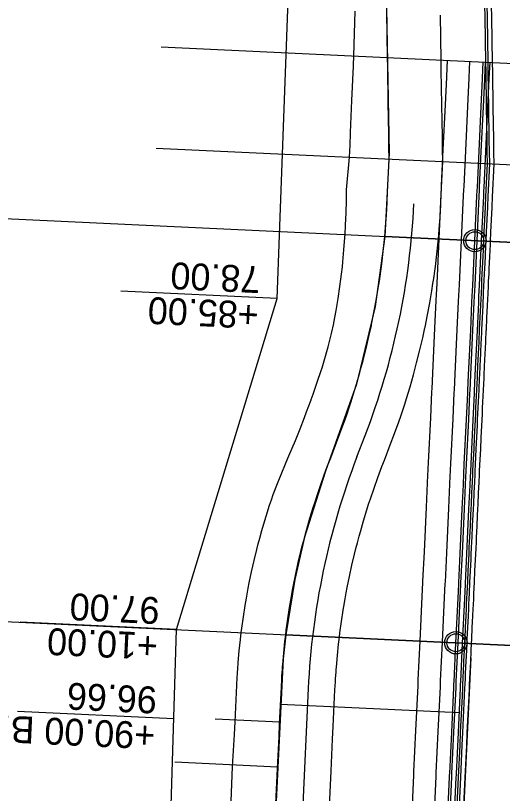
# Model space of a CAD drawing. Extents: x -70 to 701944, y -4 to 666871.
# Drawn here: x 668150.5 to 668259.3, y 654822.3 to 654996.3 of the extents above; entities that cross this region are included whole.
import ezdxf

# ---------------------------------------------------------------- set-up
doc = ezdxf.new("R2010")
doc.units = 0
for name, color, linetype in [('R_Detour', 7, 'Continuous'), ('R_Draft', 7, 'Continuous'), ('R_Drive', 7, 'Continuous'), ('R_No Plot', 7, 'Continuous'), ('R_Proposed Const Limits', 7, 'Continuous'), ('R_Proposed Road', 7, 'Continuous'), ('R_ROW', 7, 'Continuous'), ('R_ROW Annot', 7, 'Continuous'), ('R_Temp Easement Annot', 7, 'Continuous'), ('R_Water', 7, 'Continuous'), ('T_Indications', 7, 'Continuous')]:
    doc.layers.add(name, color=color, linetype=linetype)

msp = doc.modelspace()

# ---------------------------------------------------------------- linework, layer by layer
at = {"layer": 'R_Detour'}
for p, q in [((668141.87, 654951.19), (668287.62, 654944.31)), ((668134.69, 654861.43), (668283.38, 654854.41))]:
    msp.add_line(p, q, dxfattribs=at)
at = {"layer": 'R_Draft'}
msp.add_line((668181.94, 654966.65), (668374.52, 654957.56), dxfattribs=at)
at = {"layer": 'R_Drive'}
for p, q in [((668249.68, 654840.35), (668209.73, 654842.23)), ((668209.07, 654828.25), (668186.07, 654829.34))]:
    msp.add_line(p, q, dxfattribs=at)
at = {"layer": 'R_No Plot'}
for p, q in [((668183.01, 654989.3), (668375.59, 654980.21)), ((668226.79, 654897.57), (668228.65, 654902.41)), ((668215.9, 654845.79), (668212.3, 654769.57)), ((668209.54, 654838.24), (668195.13, 654838.92))]:
    msp.add_line(p, q, dxfattribs=at)
for points in [[(668285.78, 655094.57), (668215.37, 655097.89), (668216.15, 655093.84), (668225.15, 655058.76), (668230.84, 655034.55), (668233.09, 655014.27), (668233.65, 654985.81), (668233.98, 654965.53), (668233.02, 654946.89), (668287.62, 654944.31), (668288.46, 654962.05), (668284.23, 655062.51)], [(668287.62, 654944.31), (668233.02, 654946.89), (668230.85, 654931.25), (668226.69, 654913.85), (668219.8, 654894.39), (668215.11, 654879.67), (668212.9, 654870.19), (668210.9, 654857.84), (668283.38, 654854.41)], [(668210.9, 654857.84), (668210.34, 654852.46), (668208.34, 654812.91), (668206.56, 654775.07), (668206.14, 654761), (668206.78, 654747.91), (668278.19, 654744.54), (668283.38, 654854.41)]]:
    msp.add_lwpolyline(points, close=True, dxfattribs=at)
for centre in [(668253.16, 654945.94), (668248.92, 654856.04)]:
    msp.add_circle(centre, 2.5, dxfattribs=at)
for centre, start, end in [((668073.72, 654962.02), 338.9555, 357.2978), ((668381.72, 654837.96), 158.9555, 177.2978)]:
    msp.add_arc(centre, 166, start, end, dxfattribs=at)
at = {"layer": 'R_Proposed Const Limits'}
msp.add_lwpolyline([(668198.67, 654820.55), (668199, 654828.36), (668199.44, 654835.49), (668199.44, 654835.52), (668199.57, 654838.35), (668199.95, 654846.54), (668200.04, 654848.34), (668200.09, 654849.1), (668200.19, 654850.53), (668200.2, 654850.67), (668200.23, 654851.07), (668200.23, 654851.11), (668200.27, 654851.65), (668200.49, 654854.2), (668200.76, 654856.75), (668200.94, 654858.31), (668201.07, 654859.29), (668201.42, 654861.83), (668201.82, 654864.36), (668202.1, 654866), (668202.1, 654866.04), (668202.26, 654866.89), (668202.51, 654868.24), (668202.74, 654869.4), (668203.26, 654871.91), (668203.82, 654874.41), (668204.42, 654876.91), (668204.74, 654878.15), (668205.07, 654879.39), (668205.48, 654880.87), (668205.48, 654880.88), (668205.76, 654881.86), (668206.49, 654884.32), (668207.26, 654886.77), (668207.68, 654888.02), (668208.1, 654889.2), (668209.02, 654891.63), (668209.98, 654894.03), (668210.65, 654895.64), (668210.65, 654895.65), (668210.98, 654896.43), (668211.59, 654897.85), (668213.05, 654901.26), (668214.09, 654903.83), (668215.08, 654906.42), (668215.56, 654907.67), (668216.08, 654909.02), (668216.58, 654910.37), (668216.58, 654910.39), (668217.03, 654911.64), (668217.94, 654914.27), (668218.8, 654916.91), (668219, 654917.52), (668219.62, 654919.56), (668220.36, 654922.23), (668221.04, 654924.9), (668221.11, 654925.19), (668221.11, 654925.19), (668221.63, 654927.41), (668221.67, 654927.59), (668222.19, 654930.29), (668222.63, 654933), (668223.01, 654935.72), (668223.22, 654937.34), (668223.36, 654938.45), (668223.54, 654940.09), (668223.54, 654940.09), (668223.65, 654941.18), (668223.9, 654943.91), (668224.1, 654946.66), (668224.15, 654947.31), (668224.26, 654949.4), (668224.37, 654952.15), (668224.44, 654954.91), (668224.44, 654955.05), (668224.44, 654955.08), (668224.47, 654957.31), (668225.16, 654964.6), (668225.26, 654967.28), (668225.37, 654969.98), (668225.38, 654970.1), (668225.68, 654977.27), (668226, 654984.96), (668226.01, 654985.08), (668226.1, 654987.26), (668226.39, 654997.26)], dxfattribs=at)
at = {"layer": 'R_Proposed Road'}
msp.add_line((668252.26, 654852.63), (668248.08, 654764.08), dxfattribs=at)
for points in [[(668249.14, 654818.17), (668249.5, 654825.98), (668249.84, 654833.11), (668249.84, 654833.14), (668249.98, 654835.97), (668250.36, 654844.16), (668250.45, 654845.96), (668250.48, 654846.72), (668250.55, 654848.15), (668250.56, 654848.29), (668250.58, 654848.7), (668250.58, 654848.73), (668250.6, 654849.28), (668250.72, 654851.83), (668250.84, 654854.39), (668250.92, 654855.95), (668250.96, 654856.94), (668251.09, 654859.49), (668251.21, 654862.03), (668251.28, 654863.68), (668251.28, 654863.72), (668251.32, 654864.57), (668251.39, 654865.94), (668251.44, 654867.1), (668251.56, 654869.63), (668251.68, 654872.15), (668251.8, 654874.67), (668251.86, 654875.92), (668251.92, 654877.18), (668251.99, 654878.68), (668251.99, 654878.68), (668252.04, 654879.68), (668252.16, 654882.17), (668252.27, 654884.65), (668252.33, 654885.91), (668252.39, 654887.11), (668252.51, 654889.57), (668252.62, 654892.02), (668252.7, 654893.66), (668252.7, 654893.67), (668252.74, 654894.45), (668252.8, 654895.9), (668252.97, 654899.37), (668253.09, 654901.99), (668253.22, 654904.62), (668253.28, 654905.89), (668253.34, 654907.26), (668253.4, 654908.64), (668253.41, 654908.66), (668253.47, 654909.92), (668253.59, 654912.58), (668253.72, 654915.26), (668253.75, 654915.88), (668253.84, 654917.95), (668253.97, 654920.64), (668254.1, 654923.34), (668254.11, 654923.63), (668254.11, 654923.63), (668254.22, 654925.87), (668254.23, 654926.06), (668254.36, 654928.77), (668254.48, 654931.5), (668254.61, 654934.23), (668254.69, 654935.86), (668254.74, 654936.96), (668254.82, 654938.61), (668254.82, 654938.61), (668254.87, 654939.7), (668255, 654942.45), (668255.13, 654945.19), (668255.16, 654945.85), (668255.26, 654947.94), (668255.39, 654950.69), (668255.52, 654953.44), (668255.53, 654953.58), (668255.53, 654953.61), (668255.63, 654955.84), (668255.98, 654963.15), (668255.93, 654965.83), (668255.89, 654968.54), (668255.89, 654968.66), (668255.77, 654975.85), (668255.65, 654983.56), (668255.65, 654983.68), (668255.61, 654985.87), (668255.45, 654995.89), (668255.41, 654998.61)], [(668249.63, 654818.15), (668250, 654825.96), (668250.34, 654833.09), (668250.34, 654833.12), (668250.47, 654835.95), (668250.86, 654844.14), (668250.95, 654845.93), (668250.98, 654846.69), (668251.05, 654848.13), (668251.06, 654848.27), (668251.08, 654848.67), (668251.08, 654848.71), (668251.1, 654849.25), (668251.22, 654851.81), (668251.34, 654854.36), (668251.42, 654855.92), (668251.46, 654856.91), (668251.58, 654859.46), (668251.7, 654862.01), (668251.78, 654863.65), (668251.78, 654863.69), (668251.82, 654864.55), (668251.89, 654865.91), (668251.94, 654867.08), (668252.06, 654869.61), (668252.18, 654872.13), (668252.3, 654874.65), (668252.36, 654875.9), (668252.42, 654877.15), (668252.49, 654878.65), (668252.49, 654878.66), (668252.54, 654879.65), (668252.65, 654882.14), (668252.77, 654884.62), (668252.83, 654885.89), (668252.89, 654887.09), (668253, 654889.55), (668253.12, 654892), (668253.2, 654893.64), (668253.2, 654893.64), (668253.23, 654894.43), (668253.3, 654895.88), (668253.47, 654899.35), (668253.59, 654901.97), (668253.71, 654904.6), (668253.77, 654905.87), (668253.84, 654907.24), (668253.9, 654908.61), (668253.91, 654908.63), (668253.96, 654909.89), (668254.09, 654912.56), (668254.22, 654915.24), (668254.25, 654915.86), (668254.34, 654917.92), (668254.47, 654920.62), (668254.6, 654923.32), (668254.61, 654923.6), (668254.61, 654923.61), (668254.72, 654925.85), (668254.73, 654926.03), (668254.85, 654928.75), (668254.98, 654931.48), (668255.11, 654934.21), (668255.19, 654935.83), (668255.24, 654936.94), (668255.32, 654938.59), (668255.32, 654938.59), (668255.37, 654939.68), (668255.5, 654942.42), (668255.63, 654945.17), (668255.66, 654945.82), (668255.76, 654947.92), (668255.89, 654950.67), (668256.02, 654953.42), (668256.03, 654953.56), (668256.03, 654953.59), (668256.13, 654955.81), (668256.48, 654963.12), (668256.43, 654965.81), (668256.39, 654968.51), (668256.39, 654968.63), (668256.27, 654975.83), (668256.15, 654983.54), (668256.15, 654983.66), (668256.11, 654985.85), (668255.95, 654995.87), (668255.91, 654998.58)], [(668250.63, 654818.1), (668251, 654825.91), (668251.34, 654833.04), (668251.34, 654833.07), (668251.47, 654835.9), (668251.86, 654844.09), (668251.94, 654845.89), (668251.98, 654846.65), (668252.05, 654848.08), (668252.06, 654848.22), (668252.07, 654848.63), (668252.08, 654848.66), (668252.1, 654849.2), (668252.22, 654851.76), (668252.34, 654854.31), (668252.42, 654855.88), (668252.46, 654856.87), (668252.58, 654859.41), (668252.7, 654861.96), (668252.78, 654863.61), (668252.78, 654863.65), (668252.82, 654864.5), (668252.89, 654865.87), (668252.94, 654867.03), (668253.06, 654869.56), (668253.18, 654872.08), (668253.3, 654874.6), (668253.36, 654875.85), (668253.42, 654877.11), (668253.49, 654878.61), (668253.49, 654878.61), (668253.54, 654879.6), (668253.65, 654882.09), (668253.77, 654884.57), (668253.83, 654885.84), (668253.89, 654887.04), (668254, 654889.5), (668254.12, 654891.95), (668254.2, 654893.59), (668254.2, 654893.6), (668254.23, 654894.38), (668254.3, 654895.83), (668254.47, 654899.3), (668254.59, 654901.92), (668254.71, 654904.55), (668254.77, 654905.82), (668254.84, 654907.19), (668254.9, 654908.56), (668254.9, 654908.59), (668254.96, 654909.85), (668255.09, 654912.51), (668255.22, 654915.19), (668255.25, 654915.81), (668255.34, 654917.87), (668255.47, 654920.57), (668255.6, 654923.27), (668255.61, 654923.56), (668255.61, 654923.56), (668255.72, 654925.8), (668255.73, 654925.99), (668255.85, 654928.7), (668255.98, 654931.43), (668256.11, 654934.16), (668256.19, 654935.79), (668256.24, 654936.89), (668256.32, 654938.54), (668256.32, 654938.54), (668256.37, 654939.63), (668256.5, 654942.38), (668256.63, 654945.12), (668256.66, 654945.78), (668256.76, 654947.87), (668256.89, 654950.62), (668257.02, 654953.37), (668257.02, 654953.51), (668257.03, 654953.54), (668257.13, 654955.76), (668257.48, 654963.08), (668257.43, 654965.76), (668257.39, 654968.46), (668257.39, 654968.59), (668257.27, 654975.78), (668257.15, 654983.49), (668257.15, 654983.61), (668257.11, 654985.8), (668256.95, 654995.82), (668256.91, 654998.54)], [(668208.68, 654820.08), (668209.05, 654827.89), (668209.39, 654835.02), (668209.39, 654835.05), (668209.52, 654837.88), (668209.91, 654846.07), (668210, 654847.87), (668210.05, 654848.63), (668210.14, 654850.06), (668210.16, 654850.2), (668210.19, 654850.6), (668210.19, 654850.64), (668210.23, 654851.18), (668210.45, 654853.73), (668210.72, 654856.28), (668210.9, 654857.84), (668211.02, 654858.82), (668211.37, 654861.36), (668211.75, 654863.89), (668212.02, 654865.53), (668212.03, 654865.57), (668212.18, 654866.42), (668212.42, 654867.77), (668212.65, 654868.94), (668213.15, 654871.45), (668213.7, 654873.95), (668214.29, 654876.44), (668214.59, 654877.68), (668214.91, 654878.92), (668215.31, 654880.41), (668215.31, 654880.41), (668215.58, 654881.4), (668216.29, 654883.86), (668217.03, 654886.31), (668217.43, 654887.56), (668217.81, 654888.75), (668218.64, 654891.17), (668219.5, 654893.58), (668220.1, 654895.2), (668220.1, 654895.21), (668220.4, 654895.98), (668220.95, 654897.41), (668222.26, 654900.82), (668223.23, 654903.4), (668224.16, 654905.99), (668224.59, 654907.25), (668225.04, 654908.6), (668225.48, 654909.95), (668225.49, 654909.97), (668225.89, 654911.22), (668226.69, 654913.85), (668227.45, 654916.5), (668227.62, 654917.11), (668228.16, 654919.16), (668228.84, 654921.83), (668229.47, 654924.51), (668229.53, 654924.79), (668229.53, 654924.79), (668230.02, 654927.01), (668230.06, 654927.2), (668230.6, 654929.9), (668231.1, 654932.6), (668231.56, 654935.32), (668231.81, 654936.94), (668231.97, 654938.04), (668232.2, 654939.68), (668232.2, 654939.68), (668232.35, 654940.77), (668232.67, 654943.5), (668232.96, 654946.24), (668233.02, 654946.89), (668233.2, 654948.98), (668233.39, 654951.73), (668233.54, 654954.48), (668233.55, 654954.62), (668233.55, 654954.65), (668233.66, 654956.87), (668234, 654964.18), (668233.96, 654966.87), (668233.92, 654969.57), (668233.91, 654969.69), (668233.8, 654976.89), (668233.67, 654984.6), (668233.67, 654984.72), (668233.64, 654986.91), (668233.48, 654996.93)], [(668220.67, 654819.51), (668221.04, 654827.32), (668221.37, 654834.46), (668221.37, 654834.49), (668221.51, 654837.31), (668221.89, 654845.5), (668221.99, 654847.3), (668222.03, 654848.06), (668222.13, 654849.49), (668222.14, 654849.63), (668222.17, 654850.04), (668222.17, 654850.08), (668222.22, 654850.61), (668222.44, 654853.17), (668222.7, 654855.71), (668222.88, 654857.27), (668223.01, 654858.26), (668223.35, 654860.79), (668223.74, 654863.33), (668224.01, 654864.97), (668224.02, 654865), (668224.17, 654865.85), (668224.41, 654867.21), (668224.63, 654868.37), (668225.14, 654870.88), (668225.69, 654873.38), (668226.27, 654875.87), (668226.58, 654877.12), (668226.9, 654878.36), (668227.29, 654879.84), (668227.3, 654879.85), (668227.57, 654880.83), (668228.27, 654883.29), (668229.02, 654885.74), (668229.41, 654887), (668229.8, 654888.18), (668230.62, 654890.61), (668231.49, 654893.02), (668232.09, 654894.63), (668232.09, 654894.64), (668232.39, 654895.41), (668232.94, 654896.84), (668234.25, 654900.26), (668235.22, 654902.83), (668236.14, 654905.43), (668236.58, 654906.68), (668237.03, 654908.03), (668237.47, 654909.39), (668237.48, 654909.41), (668237.87, 654910.65), (668238.67, 654913.29), (668239.43, 654915.93), (668239.6, 654916.55), (668240.15, 654918.59), (668240.82, 654921.26), (668241.45, 654923.94), (668241.52, 654924.22), (668241.52, 654924.22), (668242, 654926.45), (668242.04, 654926.63), (668242.59, 654929.33), (668243.09, 654932.04), (668243.55, 654934.75), (668243.8, 654936.37), (668243.96, 654937.47), (668244.19, 654939.11), (668244.19, 654939.11), (668244.33, 654940.2), (668244.66, 654942.93), (668244.94, 654945.67), (668245, 654946.33), (668245.18, 654948.42), (668245.38, 654951.16), (668245.53, 654953.91), (668245.54, 654954.05), (668245.54, 654954.08), (668245.64, 654956.31), (668245.99, 654963.62), (668245.95, 654966.3), (668245.9, 654969.01), (668245.9, 654969.13), (668245.78, 654976.32), (668245.66, 654984.03), (668245.66, 654984.15), (668245.62, 654986.34), (668245.46, 654996.36)]]:
    msp.add_lwpolyline(points, dxfattribs=at)
at = {"layer": 'R_ROW'}
msp.add_lwpolyline([(668327.66, 653586.02), (668340.87, 653592.64), (668322.47, 653689.42), (668277.13, 653821.63), (668258.71, 653853.34), (668224.55, 653854.19), (668177.85, 653978.14), (668204.74, 653982.28), (668180.35, 654097), (668169.32, 654193.98), (668198.41, 654666.21), (668182.92, 654741.02), (668186.49, 654858.99), (668209, 654933.01), (668212.48, 655027.95)], dxfattribs=at)
at = {"layer": 'R_ROW Annot'}
msp.add_lwpolyline([(668185.89, 654838.99), (668150.92, 654840.64)], dxfattribs=at)
at = {"layer": 'R_Temp Easement Annot'}
for points in [[(668209, 654933.01), (668174.04, 654934.66)], [(668186.49, 654858.99), (668151.53, 654860.64)]]:
    msp.add_lwpolyline(points, dxfattribs=at)
at = {"layer": 'R_Water'}
for centre in [(668253.16, 654945.94), (668248.92, 654856.04)]:
    msp.add_circle(centre, 2, dxfattribs=at)
at = {"layer": 'T_Indications'}
for points in [[(668239.04, 654816.46), (668239.51, 654826.45), (668239.53, 654826.83), (668239.55, 654827.17), (668239.98, 654836.44), (668240.46, 654846.43), (668240.49, 654847.24), (668240.52, 654847.76), (668240.93, 654856.42), (668241.4, 654866.41), (668241.54, 654869.49), (668241.56, 654869.83), (668241.87, 654876.4), (668242.34, 654886.38), (668242.59, 654891.74), (668242.6, 654891.9), (668242.81, 654896.37), (668243.28, 654906.36), (668243.56, 654912.24), (668243.59, 654912.83), (668243.76, 654916.35), (668244.23, 654926.34), (668244.52, 654932.57), (668244.59, 654933.92), (668244.7, 654936.33), (668245.17, 654946.32), (668245.64, 654956.31), (668245.7, 654957.53), (668245.73, 654958.27), (668246.11, 654966.3), (668246.58, 654976.28), (668246.88, 654982.49), (668246.88, 654982.62), (668247.06, 654986.27), (668247.06, 654986.28)], [(668244.04, 654816.23), (668244.51, 654826.22), (668244.53, 654826.6), (668244.54, 654826.94), (668244.98, 654836.2), (668245.45, 654846.19), (668245.49, 654847), (668245.51, 654847.52), (668245.92, 654856.18), (668246.39, 654866.17), (668246.54, 654869.26), (668246.56, 654869.59), (668246.86, 654876.16), (668247.34, 654886.15), (668247.59, 654891.51), (668247.6, 654891.66), (668247.81, 654896.14), (668248.28, 654906.13), (668248.56, 654912), (668248.58, 654912.6), (668248.75, 654916.12), (668249.22, 654926.1), (668249.52, 654932.34), (668249.58, 654933.68), (668249.69, 654936.09), (668250.16, 654946.08), (668250.64, 654956.07), (668250.69, 654957.29), (668250.73, 654958.03), (668251.11, 654966.06), (668251.58, 654976.05), (668251.87, 654982.25), (668251.88, 654982.39), (668252.05, 654986.04), (668252.05, 654986.04)], [(668247.03, 654816.09), (668247.5, 654826.07), (668247.52, 654826.46), (668247.54, 654826.8), (668247.98, 654836.06), (668248.45, 654846.05), (668248.49, 654846.86), (668248.51, 654847.38), (668248.92, 654856.04), (668249.39, 654866.03), (668249.54, 654869.11), (668249.55, 654869.45), (668249.86, 654876.02), (668250.33, 654886.01), (668250.59, 654891.37), (668250.59, 654891.52), (668250.8, 654896), (668251.28, 654905.99), (668251.55, 654911.86), (668251.58, 654912.45), (668251.75, 654915.97), (668252.22, 654925.96), (668252.51, 654932.19), (668252.58, 654933.54), (668252.69, 654935.95), (668253.16, 654945.94), (668253.63, 654955.93), (668253.69, 654957.15), (668253.73, 654957.89), (668254.1, 654965.92), (668254.58, 654975.91), (668254.87, 654982.11), (668254.88, 654982.25), (668255.05, 654985.9), (668255.05, 654985.9)], [(668247.53, 654816.06), (668248, 654826.05), (668248.02, 654826.43), (668248.04, 654826.77), (668248.48, 654836.04), (668248.95, 654846.03), (668248.99, 654846.84), (668249.01, 654847.36), (668249.42, 654856.02), (668249.89, 654866.01), (668250.04, 654869.09), (668250.05, 654869.43), (668250.36, 654876), (668250.83, 654885.98), (668251.09, 654891.34), (668251.09, 654891.5), (668251.3, 654895.97), (668251.78, 654905.96), (668252.05, 654911.83), (668252.08, 654912.43), (668252.25, 654915.95), (668252.72, 654925.94), (668253.01, 654932.17), (668253.08, 654933.52), (668253.19, 654935.93), (668253.66, 654945.92), (668254.13, 654955.91), (668254.19, 654957.13), (668254.23, 654957.87), (668254.6, 654965.9), (668255.08, 654975.88), (668255.37, 654982.09), (668255.37, 654982.22), (668255.55, 654985.87)], [(668248.53, 654816.01), (668249, 654826), (668249.02, 654826.39), (668249.04, 654826.72), (668249.47, 654835.99), (668249.95, 654845.98), (668249.98, 654846.79), (668250.01, 654847.31), (668250.42, 654855.97), (668250.89, 654865.96), (668251.03, 654869.04), (668251.05, 654869.38), (668251.36, 654875.95), (668251.83, 654885.94), (668252.08, 654891.3), (668252.09, 654891.45), (668252.3, 654895.93), (668252.77, 654905.91), (668253.05, 654911.79), (668253.08, 654912.38), (668253.25, 654915.9), (668253.72, 654925.89), (668254.01, 654932.12), (668254.07, 654933.47), (668254.19, 654935.88), (668254.66, 654945.87), (668255.13, 654955.86), (668255.19, 654957.08), (668255.22, 654957.82), (668255.6, 654965.85), (668256.07, 654975.84), (668256.37, 654982.04), (668256.37, 654982.18), (668256.55, 654985.83), (668256.55, 654985.83)]]:
    msp.add_lwpolyline(points, dxfattribs=at)

# ---------------------------------------------------------------- texts
at = {"layer": 'R_ROW Annot'}
for s, p in [('96.66', (668182.22, 654846.17)), ('+90.00 BEGIN C/A', (668181.84, 654838.18))]:
    msp.add_text(s, height=6, rotation=177.2978, dxfattribs=at).set_placement(p)
at = {"layer": 'R_Temp Easement Annot'}
for s, p in [('78.00', (668205.34, 654940.19)), ('+85.00', (668204.96, 654932.2)), ('97.00', (668182.82, 654866.17)), ('+10.00', (668182.45, 654858.18))]:
    msp.add_text(s, height=6, rotation=177.2978, dxfattribs=at).set_placement(p)

doc.saveas('drawing.dxf')
